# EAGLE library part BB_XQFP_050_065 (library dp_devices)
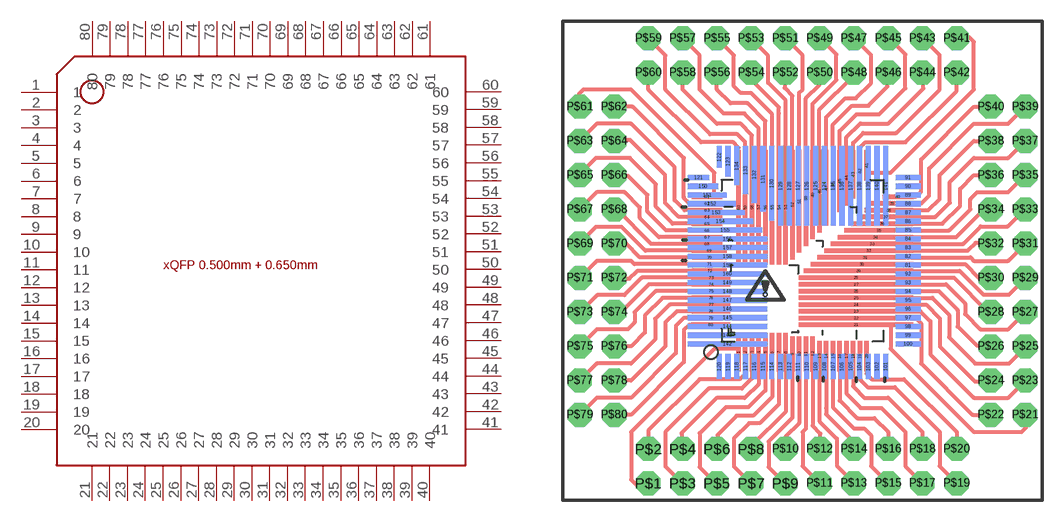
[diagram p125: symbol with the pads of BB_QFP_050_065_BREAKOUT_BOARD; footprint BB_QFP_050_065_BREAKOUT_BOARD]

Designator prefix IC

## BB_XQFP_050_065  [BB_QFP_050_065_BREAKOUT_BOARD]
1  1
2  2
3  3
4  4
5  5
6  6
7  7
8  8
9  9
10  10
11  11
12  12
13  13
14  14
15  15
16  16
17  17
18  18
19  19
20  20
21  21
22  22
23  23
24  24
25  25
26  26
27  27
28  28
29  29
30  30
31  31
32  32
33  33
34  34
35  35
36  36
37  37
38  38
39  39
40  40
41  41
42  42
43  43
44  44
45  45
46  46
47  47
48  48
49  49
50  50
51  51
52  52
53  53
54  54
55  55
56  56
57  57
58  58
59  59
60  60
61  61
62  62
63  63
64  64
65  65
66  66
67  67
68  68
69  69
70  70
71  71
72  72
73  73
74  74
75  75
76  76
77  77
78  78
79  79
80  80

## Footprint BB_QFP_050_065_BREAKOUT_BOARD (pad centres in mm)
QFP 0.5 mm pitch 32p (5mm sq) 48p (7mm sq) 64p (10mm sq) 80p (12mm sq) QFP 0.65 mm pitch 52p (10mm sq) 80p (14mm sq) CC-BY-SA
smd 0.33 x 2.824: 1 -4.75,-6.788; 2 -4.25,-6.788; 3 -3.75,-6.788; 4 -3.25,-6.788; 5 -2.75,-6.788; 6 -2.25,-6.788; 7 -1.75,-6.788; 8 -1.25,-6.788
smd 0.33 x 2.6: 9 -0.75,-6.9; 10 -0.25,-6.9; 11 0.25,-6.9; 12 0.75,-6.9
smd 0.33 x 2.25: 13 1.25,-7.075; 14 1.75,-7.075; 15 2.25,-7.075; 16 2.75,-7.075; 17 3.25,-7.075; 18 3.75,-7.075; 19 4.25,-7.075; 20 4.75,-7.075; 41 4.75,7.075
smd 8.47 x 0.33: 21 3.965,-4.75; 22 3.965,-4.25; 23 3.965,-3.75; 24 3.965,-3.25; 25 3.965,-2.75; 26 3.965,-2.25; 27 3.965,-1.75; 28 3.965,-1.25
smd 8.1 x 0.33: 29 4.15,-0.75
smd 7.6 x 0.33: 30 4.4,-0.25
smd 7.1 x 0.33: 31 4.65,0.25
smd 6.6 x 0.33: 32 4.9,0.75
smd 6.1 x 0.33: 33 5.15,1.25
smd 5.6 x 0.33: 34 5.4,1.75
smd 5.1 x 0.33: 35 5.65,2.25
smd 4.6 x 0.33: 36 5.9,2.75
smd 4.1 x 0.33: 37 6.15,3.25
smd 3.6 x 0.33: 38 6.4,3.75
smd 3.1 x 0.33: 39 6.65,4.25
smd 2.25 x 0.33: 40 7.075,4.75; 61 -7.075,4.75; 62 -7.075,4.25; 63 -7.075,3.75; 64 -7.075,3.25; 65 -7.075,2.75; 66 -7.075,2.25; 67 -7.075,1.75; 68 -7.075,1.25
smd 0.33 x 3.1: 42 4.25,6.65
smd 0.33 x 3.6: 43 3.75,6.4
smd 0.33 x 4.1: 44 3.25,6.15
smd 0.33 x 4.6: 45 2.75,5.9
smd 0.33 x 5.1: 46 2.25,5.65
smd 0.33 x 5.6: 47 1.75,5.4
smd 0.33 x 6.1: 48 1.25,5.15
smd 0.33 x 6.6: 49 0.75,4.9
smd 0.33 x 7.1: 50 0.25,4.65
smd 0.33 x 7.6: 51 -0.25,4.4
smd 0.33 x 8.1: 52 -0.75,4.15
smd 0.33 x 8.47: 53 -1.25,3.965; 54 -1.75,3.965; 55 -2.25,3.965; 56 -2.75,3.965; 57 -3.25,3.965; 58 -3.75,3.965; 59 -4.25,3.965; 60 -4.75,3.965
smd 2.6 x 0.33: 69 -6.9,0.75; 70 -6.9,0.25; 71 -6.9,-0.25; 72 -6.9,-0.75
smd 2.824 x 0.33: 73 -6.788,-1.25; 74 -6.788,-1.75; 75 -6.788,-2.25; 76 -6.788,-2.75; 77 -6.788,-3.25; 78 -6.788,-3.75; 79 -6.788,-4.25; 80 -6.788,-4.75
smd 1.875 x 0.38 bottom: 81 7.838,-0.325; 82 7.838,0.325; 83 7.838,0.975; 84 7.838,1.625; 85 7.838,2.275; 86 7.838,2.925; 87 7.838,3.575; 88 7.838,4.225; 89 7.838,4.875; 90 7.838,5.525; 91 7.838,6.175; 92 7.838,-0.975; 93 7.838,-1.625; 94 7.838,-2.275; 95 7.838,-2.925; 96 7.838,-3.575; 97 7.838,-4.225; 98 7.838,-4.875; 99 7.838,-5.525; 100 7.838,-6.175
smd 0.38 x 1.875 bottom: 101 6.175,-7.838; 102 5.525,-7.838; 103 4.875,-7.838; 104 4.225,-7.838; 105 3.575,-7.838; 106 2.925,-7.838; 107 2.275,-7.838; 108 1.625,-7.838; 109 0.975,-7.838; 110 0.325,-7.838; 111 -0.325,-7.838; 112 -0.975,-7.838; 113 -1.625,-7.838; 114 -2.275,-7.838; 115 -2.925,-7.838; 116 -3.575,-7.838; 117 -4.225,-7.838; 118 -4.875,-7.838; 119 -5.525,-7.838; 120 -6.175,-7.838
smd 1.6 x 0.38 bottom: 121 -7.7,6.175
smd 0.38 x 1.6 bottom: 122 -6.175,7.7
smd 0.38 x 2.25 bottom: 123 -5.525,7.375
smd 0.38 x 5.875 bottom: 124 1.625,5.563; 125 0.975,5.563; 126 0.325,5.563; 127 -0.325,5.563; 128 -0.975,5.563; 129 -1.625,5.563; 135 2.275,5.563; 136 2.925,5.563; 137 3.575,5.563; 138 4.225,5.563; 139 4.875,5.563; 140 5.525,5.563; 141 6.175,5.563
smd 0.38 x 5.5 bottom: 130 -2.275,5.75
smd 0.38 x 4.85 bottom: 131 -2.925,6.075
smd 0.38 x 4.2 bottom: 132 -3.575,6.4
smd 0.38 x 3.55 bottom: 133 -4.225,6.725
smd 0.38 x 2.9 bottom: 134 -4.875,7.05
smd 5.875 x 0.38 bottom: 142 -5.563,-6.175; 143 -5.563,-5.525; 144 -5.563,-4.875; 145 -5.563,-4.225; 146 -5.563,-3.575; 147 -5.563,-2.925; 148 -5.563,-2.275; 149 -5.563,-1.625; 156 -5.563,1.625; 157 -5.563,0.975; 158 -5.563,0.325; 159 -5.563,-0.325; 160 -5.563,-0.975
smd 2.25 x 0.38 bottom: 150 -7.375,5.525
smd 2.9 x 0.38 bottom: 151 -7.05,4.875
smd 3.55 x 0.38 bottom: 152 -6.725,4.225
smd 4.2 x 0.38 bottom: 153 -6.4,3.575
smd 4.85 x 0.38 bottom: 154 -6.075,2.925
smd 5.5 x 0.38 bottom: 155 -5.75,2.275
drill 1.016 pad 1.778 octagon: P$1 -11.43,-16.51; P$2 -11.43,-13.97; P$3 -8.89,-16.51; P$4 -8.89,-13.97; P$5 -6.35,-16.51; P$6 -6.35,-13.97; P$7 -3.81,-16.51; P$8 -3.81,-13.97; P$9 -1.27,-16.51; P$10 -1.27,-13.97; P$11 1.27,-16.51; P$12 1.27,-13.97; P$13 3.81,-16.51; P$14 3.81,-13.97; P$15 6.35,-16.51; P$16 6.35,-13.97; P$17 8.89,-16.51; P$18 8.89,-13.97; P$19 11.43,-16.51; P$20 11.43,-13.97; P$21 16.51,-11.43; P$22 13.97,-11.43; P$23 16.51,-8.89; P$24 13.97,-8.89; P$25 16.51,-6.35; P$26 13.97,-6.35; P$27 16.51,-3.81; P$28 13.97,-3.81; P$29 16.51,-1.27; P$30 13.97,-1.27; P$31 16.51,1.27; P$32 13.97,1.27; P$33 16.51,3.81; P$34 13.97,3.81; P$35 16.51,6.35; P$36 13.97,6.35; P$37 16.51,8.89; P$38 13.97,8.89; P$39 16.51,11.43; P$40 13.97,11.43; P$41 11.43,16.51; P$42 11.43,13.97; P$43 8.89,16.51; P$44 8.89,13.97; P$45 6.35,16.51; P$46 6.35,13.97; P$47 3.81,16.51; P$48 3.81,13.97; P$49 1.27,16.51; P$50 1.27,13.97; P$51 -1.27,16.51; P$52 -1.27,13.97; P$53 -3.81,16.51; P$54 -3.81,13.97; P$55 -6.35,16.51; P$56 -6.35,13.97; P$57 -8.89,16.51; P$58 -8.89,13.97; P$59 -11.43,16.51; P$60 -11.43,13.97; P$61 -16.51,11.43; P$62 -13.97,11.43; P$63 -16.51,8.89; P$64 -13.97,8.89; P$65 -16.51,6.35; P$66 -13.97,6.35; P$67 -16.51,3.81; P$68 -13.97,3.81; P$69 -16.51,1.27; P$70 -13.97,1.27; P$71 -16.51,-1.27; P$72 -13.97,-1.27; P$73 -16.51,-3.81; P$74 -13.97,-3.81; P$75 -16.51,-6.35; P$76 -13.97,-6.35; P$77 -16.51,-8.89; P$78 -13.97,-8.89; P$79 -16.51,-11.43; P$80 -13.97,-11.43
